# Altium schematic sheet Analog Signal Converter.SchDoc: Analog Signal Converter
size A3; CompanyName: Hitex GmbH; Address1: Greschbachstr. 12; Address2: 76229 Karlsruhe, Germany; Address3: www.hitex.com; DocumentNumber: 4; SheetNumber: 4; SheetTotal: 8; PageSetup: Record=PageOptions¦CenterHorizontal=True¦CenterVertical=True¦PrintScale=1.04¦XCorrection=1.00¦YCorrection=1.00¦PrintKind=0¦BorderSize=5000000¦LeftOffset=0¦BottomOffset=0¦Orientation=2¦PaperLength=1000¦PaperWidth=1000¦Scale=100¦PaperSource=7¦PrintQuality=1200¦MediaType=1¦DitherType=10¦PaperKind=A3¦PrintScaleMode=1
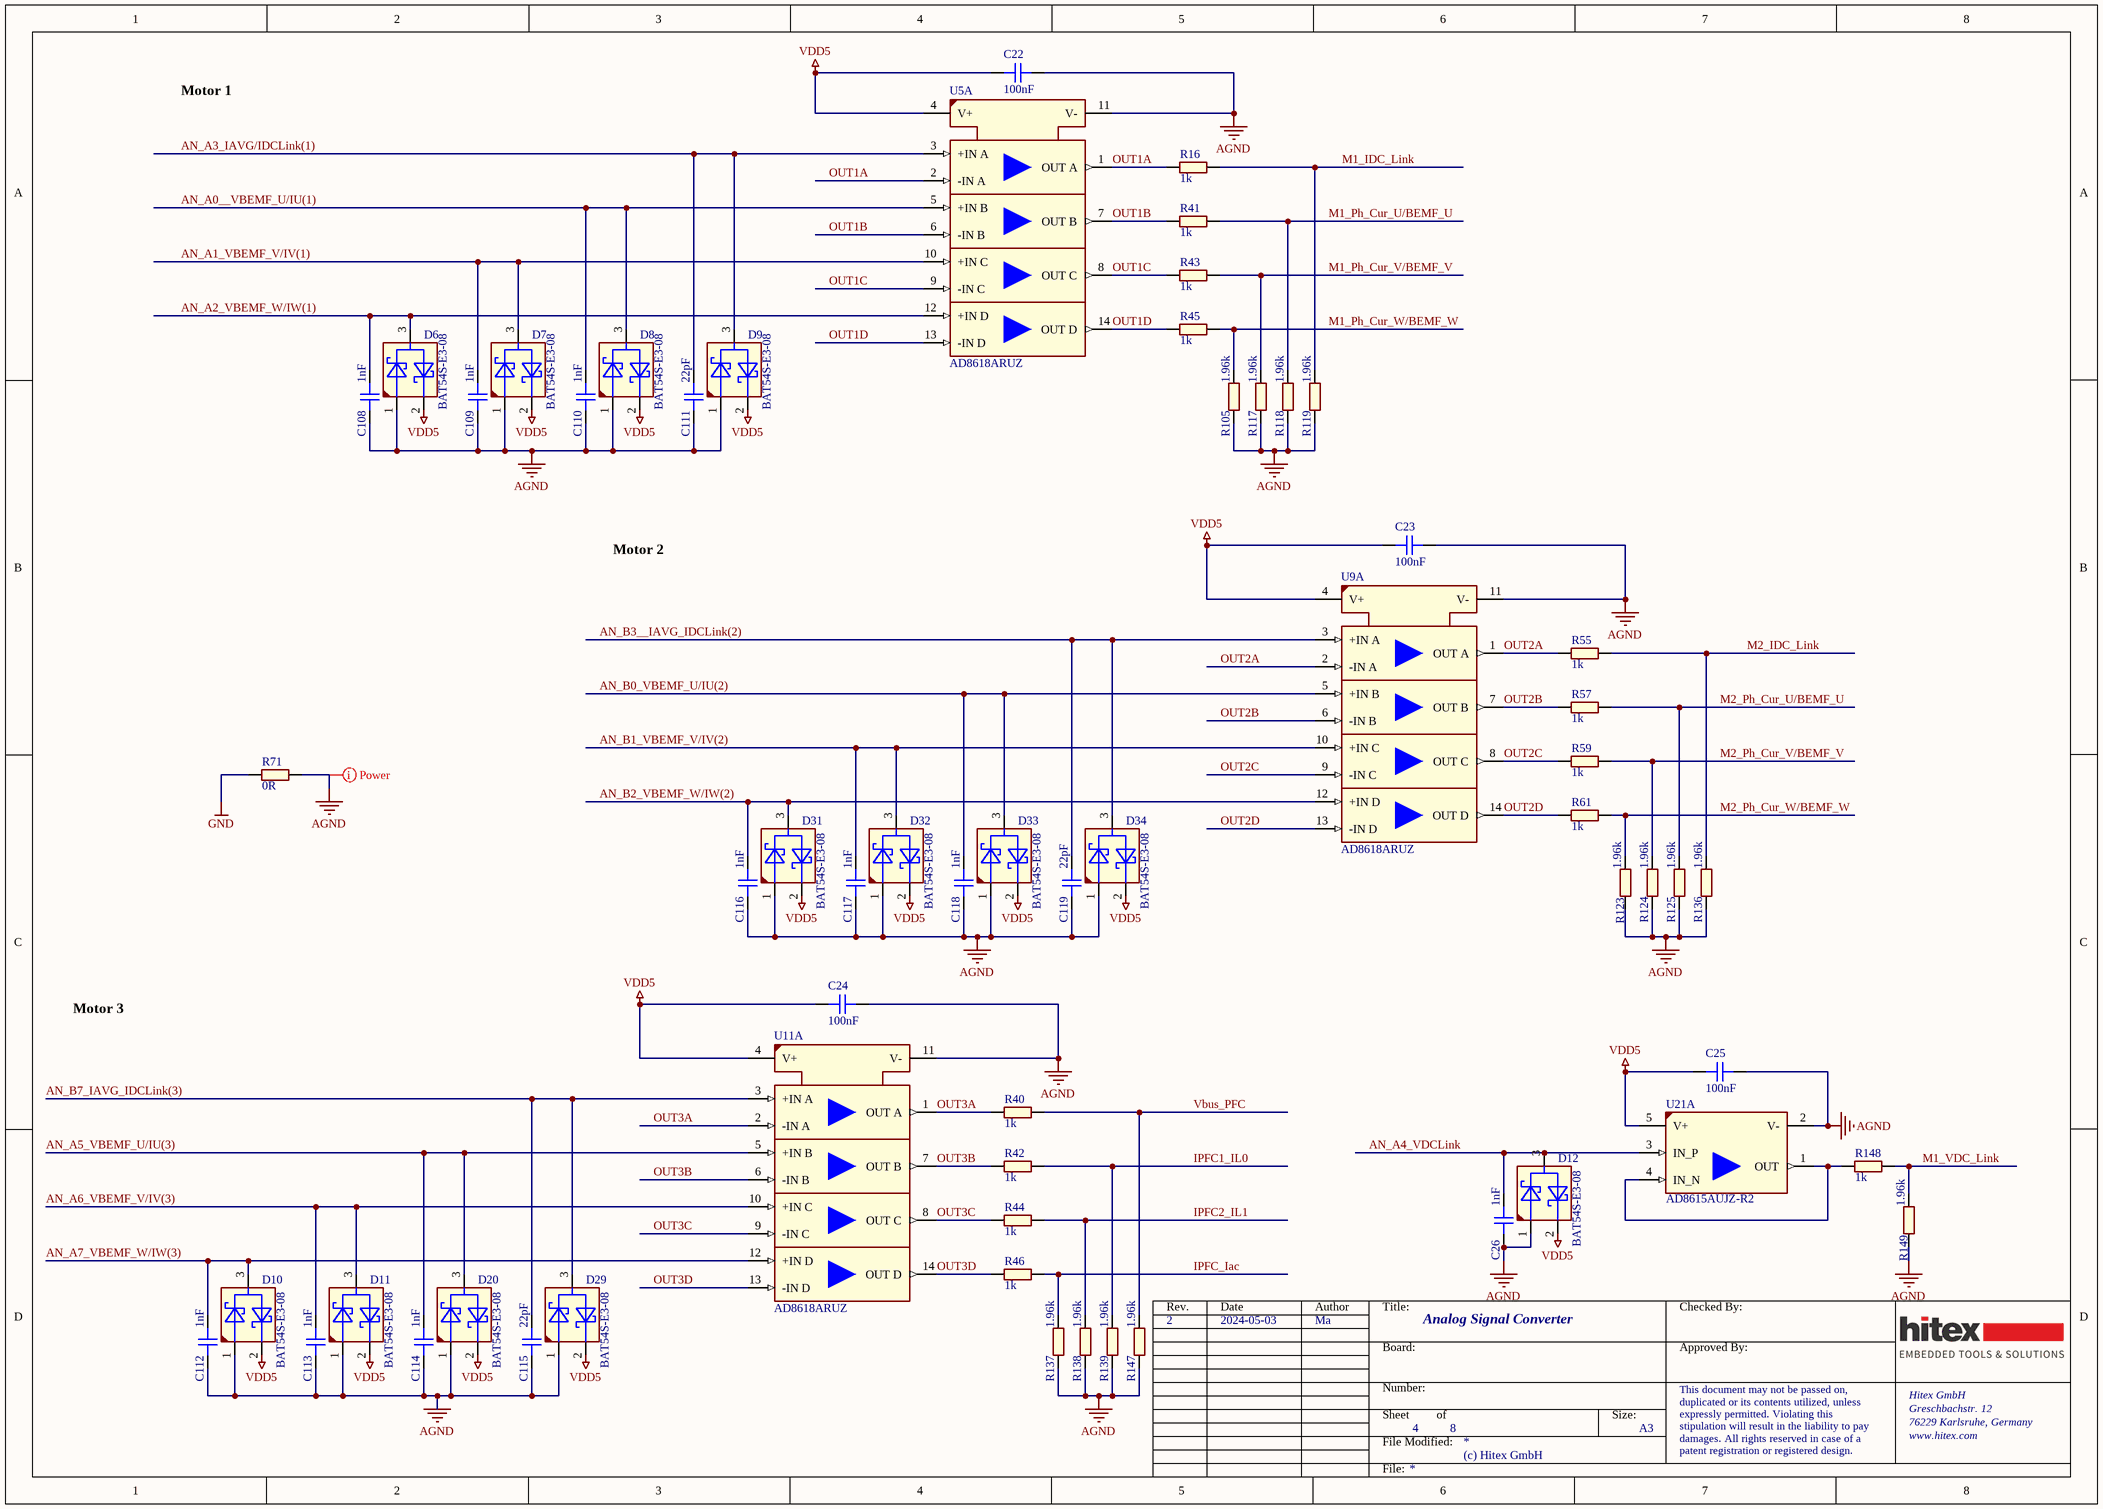
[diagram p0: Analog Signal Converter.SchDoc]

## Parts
C22  100nF  [CAPC1005X55N-0]
C23  100nF  [CAPC1005X55N-0]
C24  100nF  [CAPC1005X55N-0]
C25  100nF  [CAPC1005X55N-0]
C26  1nF  [CAPC1005X55N-0]
C108  1nF  [CAPC1005X55N-0]
C109  1nF  [CAPC1005X55N-0]
C110  1nF  [CAPC1005X55N-0]
C111  22pF  [CAPC1005X55N-0]
C112  1nF  [CAPC1005X55N-0]
C113  1nF  [CAPC1005X55N-0]
C114  1nF  [CAPC1005X55N-0]
C115  22pF  [CAPC1005X55N-0]
C116  1nF  [CAPC1005X55N-0]
C117  1nF  [CAPC1005X55N-0]
C118  1nF  [CAPC1005X55N-0]
C119  22pF  [CAPC1005X55N-0]
D6  BAT54S-E3-08  [SOT95P248X115-3N]
D7  BAT54S-E3-08  [SOT95P248X115-3N]
D8  BAT54S-E3-08  [SOT95P248X115-3N]
D9  BAT54S-E3-08  [SOT95P248X115-3N]
D10  BAT54S-E3-08  [SOT95P248X115-3N]
D11  BAT54S-E3-08  [SOT95P248X115-3N]
D12  BAT54S-E3-08  [SOT95P248X115-3N]
D20  BAT54S-E3-08  [SOT95P248X115-3N]
D29  BAT54S-E3-08  [SOT95P248X115-3N]
D31  BAT54S-E3-08  [SOT95P248X115-3N]
D32  BAT54S-E3-08  [SOT95P248X115-3N]
D33  BAT54S-E3-08  [SOT95P248X115-3N]
D34  BAT54S-E3-08  [SOT95P248X115-3N]
R16  1k  [RESC1005X40N]
R40  1k  [RESC1005X40N]
R41  1k  [RESC1005X40N]
R42  1k  [RESC1005X40N]
R43  1k  [RESC1005X40N]
R44  1k  [RESC1005X40N]
R45  1k  [RESC1005X40N]
R46  1k  [RESC1005X40N]
R55  1k  [RESC1005X40N]
R57  1k  [RESC1005X40N]
R59  1k  [RESC1005X40N]
R61  1k  [RESC1005X40N]
R71  0R  [RESC1005X03N]
R105  1.96k  [RESC1005X40N]
R117  1.96k  [RESC1005X40N]
R118  1.96k  [RESC1005X40N]
R119  1.96k  [RESC1005X40N]
R123  1.96k  [RESC1005X40N]
R124  1.96k  [RESC1005X40N]
R125  1.96k  [RESC1005X40N]
R136  1.96k  [RESC1005X40N]
R137  1.96k  [RESC1005X40N]
R138  1.96k  [RESC1005X40N]
R139  1.96k  [RESC1005X40N]
R147  1.96k  [RESC1005X40N]
R148  1k  [RESC1005X40N]
R149  1.96k  [RESC1005X40N]
U5  AD8618ARUZ  [SOP65P640X120-14N-0]  (part A of 5)
U9  AD8618ARUZ  [SOP65P640X120-14N-0]  (part A of 5)
U11  AD8618ARUZ  [SOP65P640X120-14N-0]  (part A of 5)
U21  AD8615AUJZ-R2  [SOT95P280X100-5N-0]  (part A of 2)

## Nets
AGND: C22.1 C23.1 C24.1 C25.1 C26.1 C108.1 C109.1 C110.1 C111.1 C112.1 C113.1 C114.1 C115.1 C116.1 C117.1 C118.1 C119.1 D6.1(ANODE) D7.1(ANODE) D8.1(ANODE) D9.1(ANODE) D10.1(ANODE) D11.1(ANODE) D12.1(ANODE) D20.1(ANODE) D29.1(ANODE) D31.1(ANODE) D32.1(ANODE) D33.1(ANODE) D34.1(ANODE) R71.2 R105.1 R117.1 R118.1 R119.1 R123.1 R124.1 R125.1 R136.1 R137.1 R138.1 R139.1 R147.1 R149.1 U5.11(V-) U9.11(V-) U11.11(V-) U21.2(V-)
GND: R71.1
VDD5: C22.2 C23.2 C24.2 C25.2 D6.2(CATHODE) D7.2(CATHODE) D8.2(CATHODE) D9.2(CATHODE) D10.2(CATHODE) D11.2(CATHODE) D12.2(CATHODE) D20.2(CATHODE) D29.2(CATHODE) D31.2(CATHODE) D32.2(CATHODE) D33.2(CATHODE) D34.2(CATHODE) U5.4(V+) U9.4(V+) U11.4(V+) U21.5(V+)
AN_A0__VBEMF_U/IU(1): C110.2 D8.3(AC) U5.5(+IN_B)
AN_A1_VBEMF_V/IV(1): C109.2 D7.3(AC) U5.10(+IN_C)
AN_A2_VBEMF_W/IW(1): C108.2 D6.3(AC) U5.12(+IN_D)
AN_A3_IAVG/IDCLink(1): C111.2 D9.3(AC) U5.3(+IN_A)
AN_A4_VDCLink: C26.2 D12.3(AC) U21.3(IN_P)
AN_A5_VBEMF_U/IU(3): C114.2 D20.3(AC) U11.5(+IN_B)
AN_A6_VBEMF_V/IV(3): C113.2 D11.3(AC) U11.10(+IN_C)
AN_A7_VBEMF_W/IW(3): C112.2 D10.3(AC) U11.12(+IN_D)
AN_B0_VBEMF_U/IU(2): C118.2 D33.3(AC) U9.5(+IN_B)
AN_B1_VBEMF_V/IV(2): C117.2 D32.3(AC) U9.10(+IN_C)
AN_B2_VBEMF_W/IW(2): C116.2 D31.3(AC) U9.12(+IN_D)
AN_B3__IAVG_IDCLink(2): C119.2 D34.3(AC) U9.3(+IN_A)
AN_B7_IAVG_IDCLink(3): C115.2 D29.3(AC) U11.3(+IN_A)
IPFC1_IL0: R42.2 R139.2
IPFC2_IL1: R44.2 R138.2
IPFC_Iac: R46.2 R137.2
M1_IDC_Link: R16.2 R119.2
M1_Ph_Cur_U/BEMF_U: R41.2 R118.2
M1_Ph_Cur_V/BEMF_V: R43.2 R117.2
M1_Ph_Cur_W/BEMF_W: R45.2 R105.2
M1_VDC_Link: R148.2 R149.2
M2_IDC_Link: R55.2 R136.2
M2_Ph_Cur_U/BEMF_U: R57.2 R125.2
M2_Ph_Cur_V/BEMF_V: R59.2 R124.2
M2_Ph_Cur_W/BEMF_W: R61.2 R123.2
OUT1A: R16.1 U5.1(OUT_A) U5.2(-IN_A)
OUT1B: R41.1 U5.6(-IN_B) U5.7(OUT_B)
OUT1C: R43.1 U5.8(OUT_C) U5.9(-IN_C)
OUT1D: R45.1 U5.13(-IN_D) U5.14(OUT_D)
OUT2A: R55.1 U9.1(OUT_A) U9.2(-IN_A)
OUT2B: R57.1 U9.6(-IN_B) U9.7(OUT_B)
OUT2C: R59.1 U9.8(OUT_C) U9.9(-IN_C)
OUT2D: R61.1 U9.13(-IN_D) U9.14(OUT_D)
OUT3A: R40.1 U11.1(OUT_A) U11.2(-IN_A)
OUT3B: R42.1 U11.6(-IN_B) U11.7(OUT_B)
OUT3C: R44.1 U11.8(OUT_C) U11.9(-IN_C)
OUT3D: R46.1 U11.13(-IN_D) U11.14(OUT_D)
Vbus_PFC: R40.2 R147.2
NetR148_1: R148.1 U21.1(OUT) U21.4(IN_N)

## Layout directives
net class Power: AGND

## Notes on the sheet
- Motor 1
- Motor 2
- Motor 3
- (near R147) 2
- 2024-05-03
- Ma

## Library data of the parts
C22-C25 = 310625: CAP / CERA / 100nF / 50V / 10% / X7R (EIA) / -55°C to 125°C / 0402(1005) / SMD / -; Multiple Parts: No; Legacy PartNumber: CAP01010920; Manufacturer: MuRata; Manufacturer Order Number: GRM155R71H104KE14D; Symbol Type: Capacitor; Single; Standard; 2 Pins; Alternate View: Yes; Article Number: 310625; Version Number: V01; Combined Parameters: TC:X7R (EIA);Tol.:-10%/+10%;Vdc:50V; QuickPick: 100nF / 50V / 10% / X7R (EIA) / 0402 (1005M); Type: Standard; Style: Single; Package Metric: 1005; Package Imperial: 0402; ComponentStatus: Released; PLMStatus: Active; HTX: 01.22.0596.0
C26 C108-C110 C112-C114 C116-C118 = 287086: CAP / CERA / 1nF / 50V / 10% / X7R (EIA) / -55°C to 125°C / 0402(1005) / SMD / -; Multiple Parts: No; Legacy PartNumber: CAP01006490; Manufacturer: MuRata; Manufacturer Order Number: GCM155R71H102KA37; Symbol Type: Capacitor; Single; Standard; 2 Pins; Alternate View: Yes; Article Number: 287086; Version Number: V01; Combined Parameters: TC:X7R (EIA);Tol.:-10%/+10%;Vdc:50V; QuickPick: 1nF / 50V / 10% / X7R (EIA) / 0402 (1005); Type: Standard; Style: Single; Automotive Qualified: AEC Q200; Package Metric: 1005; Package Imperial: 0402; ComponentStatus: Released; PLMStatus: Active; HTX: 01.22.0574.0
C111 C115 C119 = 286936: CAP / CERA / 22pF / 50V / 5% / C0G (EIA) / NP0 / -55°C to 125°C / 0402(1005) / SMD / -; Multiple Parts: No; Legacy PartNumber: CAP01006460; Manufacturer: MuRata; Manufacturer Order Number: GCM1555C1H220JA16; Symbol Type: Capacitor; Single; Standard; 2 Pins; Alternate View: Yes; Article Number: 286936; Version Number: V01; Combined Parameters: TC:C0G (EIA) / NP0;Tol.:-5%/+5%;Vdc:50V; QuickPick: 22pF / 50V / 5% / C0G (EIA) / NP0 / 0402 (1005); Type: Standard; Style: Single; Automotive Qualified: AEC Q200; Package Metric: 1005; Package Imperial: 0402; ComponentStatus: Released; PLMStatus: Active; HTX: 01.22.0809.0
D6-D12 D20 D29 D31-D34 = 394146: Dual Series Small Signal Schottky Diodes; Legacy PartNumber: DIO01300188; Manufacturer: Vishay; Symbol Type: Dual Schottky Diode Symbol 3 Pins, 1 Anode1 , 2 Cathode2, 3 Anode2, Cathode1; Alternate View: Yes; Article Number: 394146; Version Number: V01; Combined Parameters: Vf:800mV;If:200mA;Ur:30V;Ir:2uA;Pmax:-; QuickPick: Schottky Diode / SOT-23; Automotive Qualified: AEC Q101; ComponentStatus: Released; PLMStatus: Active; Voltage DC (max): na; HTX: 01.41.0376.0
R16 R40-R46 R55 R57 R59 R61 R148 = 341597: RES / STD / 1k / 63mW / 1% / 100ppm/K / -55°C to 155°C / 0402(1005) / SMD / -; Multiple Parts: No; Legacy PartNumber: RES01800343; Manufacturer: Vishay; Manufacturer Order Number: CRCW04021K00FK; Symbol Type: Resistor; Single; Standard; 2 Pins; Alternate View: Yes; Article Number: 341597; Version Number: V01; Combined Parameters: TCR:100ppm/K;Tol.:-1%/+1%;Vdc:50V;Idc:-;P:63mW; QuickPick: 1k / 1% / 0.063 / 0402 (1005); Style: Single; Automotive Qualified: AEC Q200; Package Metric: 1005; Package Imperial: 0402; ComponentStatus: Released; PLMStatus: Active; Voltage DC (max): 50V; HTX: 01.02.0701.0
R71 = 327372: RES / STD / 0R / 63mW / 0R / 0ppm/K / -55°C to 155°C / 0402(1005) / SMD / -; Multiple Parts: No; Legacy PartNumber: RES00000001; Manufacturer: Yageo; Manufacturer Order Number: RC0402JR-070RL; Symbol Type: Resistor; Single; Standard; 2 Pins; Alternate View: Yes; Article Number: 327372; Version Number: V01; Combined Parameters: TCR:0ppm/K;Tol.:-0R/+0R;Vdc:50V;Idc:1A;P:63mW; QuickPick: 0R / 0R / 0.063 / 0402 (1005); Style: Single; Package Metric: 1005; Package Imperial: 0402; ComponentStatus: Released; PLMStatus: Active; Voltage DC (max): 50V; HTX: 01.02.0902.0
R105 R117-R119 R123-R125 R136-R139 R147 R149 = 341752: RES / STD / 1.96k / 63mW / 1% / 100ppm/K / -55°C to 155°C / 0402(1005) / SMD / -; Multiple Parts: No; Legacy PartNumber: RES01800374; Manufacturer: Vishay; Manufacturer Order Number: CRCW04021K96FK; Symbol Type: Resistor; Single; Standard; 2 Pins; Alternate View: Yes; Article Number: 341752; Version Number: V01; Combined Parameters: TCR:100ppm/K;Tol.:-1%/+1%;Vdc:50V;Idc:-;P:63mW; QuickPick: 1.96k / 1% / 0.063 / 0402 (1005); Style: Single; Automotive Qualified: AEC Q200; Package Metric: 1005; Package Imperial: 0402; ComponentStatus: Released; PLMStatus: Active; Voltage DC (max): 50V; HTX: 01.02.0844.0
U5 U9 U11 = 403536: Precision, 20MHz, CMOS, Quad Rail-to-Rail Input/Output Operational Amplifier; Legacy PartNumber: IC02600068; Manufacturer: Analog Devices; Alternate View: yes; Symbol type: Standard symbol for AD8618 series Precision, 20MHz, CMOS, Quad Rail-to-Rail Input/Output Operational Amplifiers; Article Number: 403536; Version Number: V01; Legacy DeviceID: AD_AD8618ARUZ; Combined Parameters: Res.:-;Fmax:-; QuickPick: TSSOP-14; Automotive Qualified: No; ComponentStatus: Released; PLMStatus: Active; Voltage DC (max): na; HTX: 00.91.0096.0
U21 = 413062: Single Precision, 20MHz, CMOS, Rail-to-Rail Input/Output Operational Amplifier; Legacy PartNumber: IC02600931; Manufacturer: Analog Devices; Alternate View: Yes; Symbol Type: Precision CMOS Rail-to-Rail Input/Output Operational Amplifier; Article Number: 413062; Version Number: V01; Legacy DeviceID: AD_AD8615; Combined Parameters: Res.:-;Fmax:-; QuickPick: TSOT-23 (UJ-5); Automotive Qualified: No; ComponentStatus: Released; PLMStatus: Active; Voltage DC (max): na; HTX: 00.91.0070.0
